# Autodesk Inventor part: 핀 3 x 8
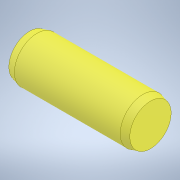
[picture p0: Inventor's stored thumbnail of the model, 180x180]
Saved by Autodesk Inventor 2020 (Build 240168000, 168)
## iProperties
Created: 2024-04
Part Number: 핀 3 x 8
Material: 강철, 연강
Description: 평행 핀
Document SubType Name: Modeling
Designer: oem
Density: 7.85 g/cm^3
Appearance: 기본값
Author: jhkim
Sending System: Autodesk Inventor 2025
Preprocessor: ST-DEVELOPER v20
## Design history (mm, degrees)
feature "Solid1"
node "솔리드1"
